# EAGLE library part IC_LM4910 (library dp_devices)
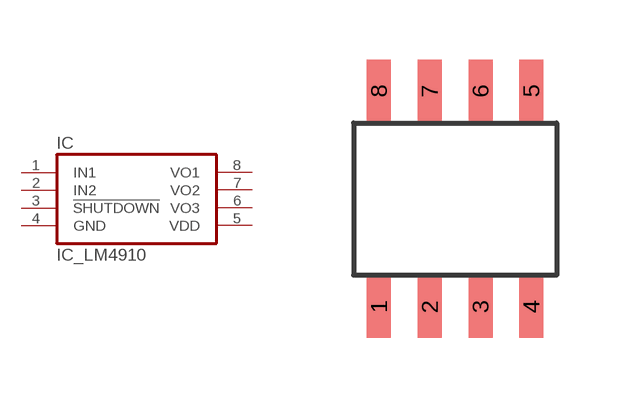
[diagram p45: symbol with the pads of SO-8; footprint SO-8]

Designator prefix IC

## IC_LM4910-SO-8  [SO-8]
1  IN1  in
2  IN2  in
3  !SHUTDOWN  in
4  GND  pwr
5  VDD  pwr
6  VO3  out
7  VO2  out
8  VO1  out

## Footprint SO-8 (pad centres in mm)
smd 0.6 x 1.55: 1 -1.905,-2.69; 2 -0.635,-2.69; 3 0.635,-2.69; 4 1.905,-2.69; 5 1.905,2.71; 6 0.635,2.71; 7 -0.635,2.71; 8 -1.905,2.71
